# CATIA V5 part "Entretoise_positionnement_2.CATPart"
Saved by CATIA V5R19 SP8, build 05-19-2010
Part number: Entretoise_positionnement_2
Bounding box of the stored display mesh (mm): x 25.547 to 59.167, y -160.247 to -140.205, z 1302.225 to 1322.225
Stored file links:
  G:\EU_thinkMotion\CFAO_2010\MMS_groupe2\MMS_groupe2\OK\nrosalie\nrosalie_cfao_support_d_arme_legere_final\Entretoise_positionnement_2.CATPart
  G:\EU_thinkMotion\CFAO_2010\MMS_groupe2\MMS_groupe2\OK\nrosalie\nrosalie_cfao_support_d_arme_legere_final\nrosalie_Support_d_arme_legere.CATProduct
  G:\EU_thinkMotion\CFAO_2010\MMS_groupe2\MMS_groupe2\OK\nrosalie\nrosalie_cfao_support_d_arme_legere_final\Arme.CATPart
  G:\EU_thinkMotion\CFAO_2010\MMS_groupe2\MMS_groupe2\OK\nrosalie\nrosalie_cfao_support_d_arme_legere_final\Bras.CATPart
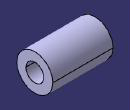
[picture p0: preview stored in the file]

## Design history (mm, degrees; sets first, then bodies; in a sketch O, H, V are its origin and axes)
Set1
  Sketch1 on face of DatumSurface1, origin (25.4041, 0.0003, 0), H (-0.0012, 1, 0), V (0, 0, 1)
    circle A1 centre (-150.2469, 1312.2253) radius 5
    reference projected circle E1 centre (-150.2469, 1312.2253) radius 5 from edge of DatumCurve1
    circle A2 centre (-150.2469, 1312.2253) radius 10
    distance A1 A2 = 5
    coincidence: A1 E1
    concentricity: A2 A1
Set2
  DatumSurface1: linked copy from another document
  DatumCurve1: linked copy from another document
  DatumSurface2: linked copy from another document
Body1 (main body)
  Pad1: profile Sketch1, direction (1, 0.0012, 0), up to face of DatumSurface2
